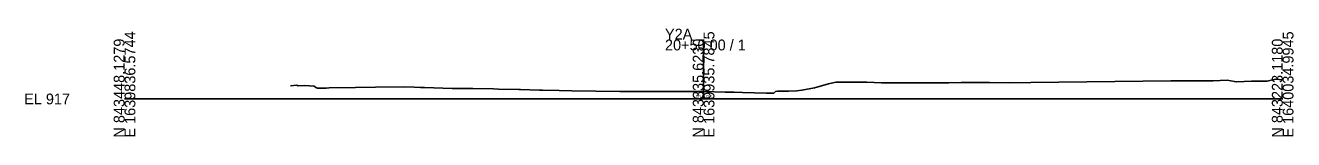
# Model space of a CAD drawing. Extents: x -26 to 303, y -10 to 10517.
# Drawn here: x -25.7 to 302.8, y 9990.3 to 10018.2 of the extents above; entities that cross this region are included whole.
import ezdxf

# ---------------------------------------------------------------- set-up
doc = ezdxf.new("R2010")
doc.units = 0
for name, color, linetype in [('Exist Cross Section Cell', 7, 'Continuous'), ('Exist XS Center Line Elevation Label', 7, 'Continuous'), ('Exist XS Ground Line', 7, 'Continuous')]:
    doc.layers.add(name, color=color, linetype=linetype)

msp = doc.modelspace()

# ---------------------------------------------------------------- linework, layer by layer
at = {"layer": 'Exist Cross Section Cell'}
for p, q in [((150, 10000), (150, 10015.37)), ((0, 10000), (150, 10000)), ((150, 10000), (300, 10000))]:
    msp.add_line(p, q, dxfattribs=at)
at = {"layer": 'Exist XS Ground Line'}
msp.add_lwpolyline([(42.99, 10003.41), (44.6, 10003.6), (44.99, 10003.36), (46.72, 10003.47), (49.13, 10003.27), (49.58, 10002.99), (49.94, 10002.77), (52.26, 10002.82), (53.03, 10002.84), (59.83, 10002.95), (65.03, 10003.02), (72.27, 10003.1), (75.06, 10003.02), (76.67, 10002.96), (77.68, 10002.94), (84.85, 10002.7), (86.37, 10002.71), (90.26, 10002.7), (95.54, 10002.58), (96.86, 10002.55), (102.1, 10002.43), (102.58, 10002.42), (107.49, 10002.29), (108.26, 10002.27), (112.57, 10002.15), (115.86, 10002.09), (128.31, 10001.89), (141.39, 10001.93), (146.67, 10001.92), (149.66, 10001.97), (150, 10001.96), (155.55, 10001.8), (157.88, 10001.73), (160.11, 10001.68), (166.31, 10001.53), (168.16, 10001.47), (168.66, 10001.97), (169.12, 10001.98), (171.98, 10002.04), (174.15, 10002.14), (175.46, 10002.26), (178.71, 10002.87), (182.32, 10003.9), (184.21, 10004.33), (186.47, 10004.38), (192.27, 10004.31), (196.08, 10004.15), (201.53, 10004.13), (211.09, 10004.18), (213.53, 10004.19), (216.7, 10004.24), (220.61, 10004.25), (224.06, 10004.29), (229.26, 10004.21), (234.78, 10004.25), (271.01, 10004.72), (281.98, 10004.71), (285.65, 10004.84), (287.49, 10004.55), (288.11, 10004.42), (291.94, 10004.58), (296.01, 10004.64), (296.99, 10004.82), (298.12, 10005.12), (300, 10004.99)], dxfattribs=at)

# ---------------------------------------------------------------- texts
at = {"layer": 'Exist Cross Section Cell'}
for s, p in [('E 1639836.5744', (2.8, 9990)), ('E 1639935.7845', (152.8, 9990)), ('E 1640034.9945', (302.8, 9990)), ('N 843448.1279', (0, 9990)), ('N 843335.6230', (150, 9990)), ('N 843223.1180', (300, 9990))]:
    msp.add_text(s, height=2.8, rotation=90, dxfattribs=at).set_placement(p)
for s, p in [('Y2A', (140, 10015.37)), ('20+50.00 / 1', (140, 10012.57)), ('EL 917', (-26, 9998.6))]:
    msp.add_text(s, height=2.8, dxfattribs=at).set_placement(p)
at = {"layer": 'Exist XS Center Line Elevation Label'}
msp.add_text('918.96', height=1, dxfattribs=at).set_placement((147.94, 9999.98))

doc.saveas('drawing.dxf')
